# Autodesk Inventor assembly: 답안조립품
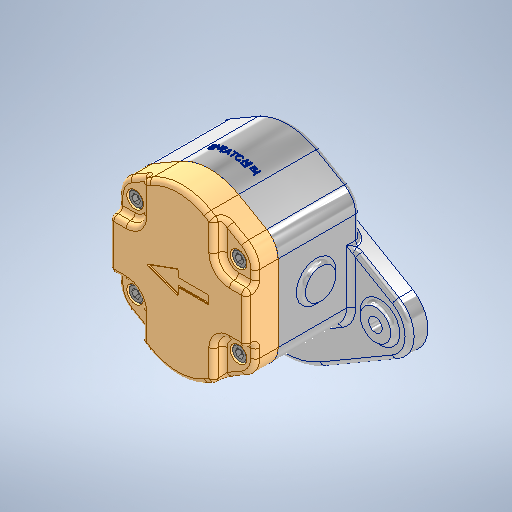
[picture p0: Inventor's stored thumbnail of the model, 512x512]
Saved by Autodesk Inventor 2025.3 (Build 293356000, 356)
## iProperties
Created: 2025-11
Part Number: 답안조립품
Document SubType Name: Assembly
Designer: PC-13
Author: PC-13
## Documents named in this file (8)
- C:\Users\PC-13\Desktop\751103V1004\답안조립품.iam
- C:\Users\PC-13\Desktop\751103V1004\답안본체.ipt
- C:\Users\PC-13\Desktop\751103V1004\DU 부시\DU 부시.ipt
- C:\Users\PC-13\Desktop\751103V1004\스퍼기어\스퍼기어.ipt
- C:\Users\PC-13\Desktop\751103V1004\구동기어\구동기어\구동기어.ipt
- C:\Users\PC-13\Desktop\751103V1004\6각 구멍붙이 볼트 M6x16\6각 구멍붙이 볼트 M6x16\6각 구멍붙이 볼트 M6x16.ipt
- C:\Users\PC-13\Desktop\751103V1004\커버\커버\커버.ipt
- C:\Users\PC-13\Desktop\751103V1004\오일 실 16 30 7\오일 실 16 30 7\오일 실 16 30 7.ipt
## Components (9 placed, 3 different names)
1. DU 부시:1
2. DU 부시:2
3. DU 부시:3
4. DU 부시:4
5. 구동기어:1
6. 6각 구멍붙이 볼트 M6x16:1
7. 6각 구멍붙이 볼트 M6x16:2
8. 6각 구멍붙이 볼트 M6x16:3
9. 6각 구멍붙이 볼트 M6x16:4
